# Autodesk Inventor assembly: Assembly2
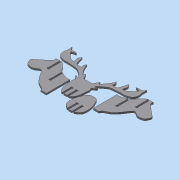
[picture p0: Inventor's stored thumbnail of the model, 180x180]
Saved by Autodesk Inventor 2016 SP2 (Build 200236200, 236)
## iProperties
Created: 2017-07
Part Number: Assembly2
Document SubType Name: Assembly
Designer: Mohamed A.
Author: Mohamed A.
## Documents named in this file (4)
- C:\Users\Mohamed\Documents\inventor\cam\Assembly2.iam
- C:\Users\Mohamed\Documents\Inventor\cam\Part1.ipt
- C:\Users\Mohamed\Documents\Inventor\cam\Part3.ipt
- C:\Users\Mohamed\Documents\Inventor\cam\Part2.ipt
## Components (4 placed, 3 different names)
1. Part1:1 — Flush:1, Flush:2, Flush:3
2. Part3:1 — Flush:2
3. Part3:2 — Flush:3
4. Part2:1 — Flush:1
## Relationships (3: Flush 3)
- Flush:1: Part1:1 ↔ Part2:1
- Flush:2: Part1:1 ↔ Part3:1
- Flush:3: Part1:1 ↔ Part3:2
